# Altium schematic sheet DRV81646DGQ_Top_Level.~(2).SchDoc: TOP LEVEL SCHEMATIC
size 431 x 279 mm; Date: Not shown in title block; ApprovedBy: Not shown in title block; CheckedBy: Not shown in title block; Author: Not shown in title block; CompanyName: Not shown in title block; DrawnBy: Mojtaba Afshar; Engineer: Not shown in title block; Organization: Not shown in title block; Address1: Not shown in title block; Address2: Not shown in title block; Address3: Not shown in title block; Address4: Not shown in title block; DocumentNumber: 2; Revision: Use project parameter SCH_Rev; SheetNumber: 0; SheetTotal: 5; PageSetup: Record=PageOptions¦CenterHorizontal=True¦CenterVertical=True¦PrintScale=1.00¦XCorrection=1.00¦YCorrection=1.00¦PrintKind=0¦BorderSize=5000000¦LeftOffset=0¦BottomOffset=0¦Orientation=2¦PaperLength=1000¦PaperWidth=1000¦Scale=100¦PaperSource=15¦PrintQuality=600¦MediaType=1¦DitherType=10¦PaperKind=Letter¦PrintScaleMode=1
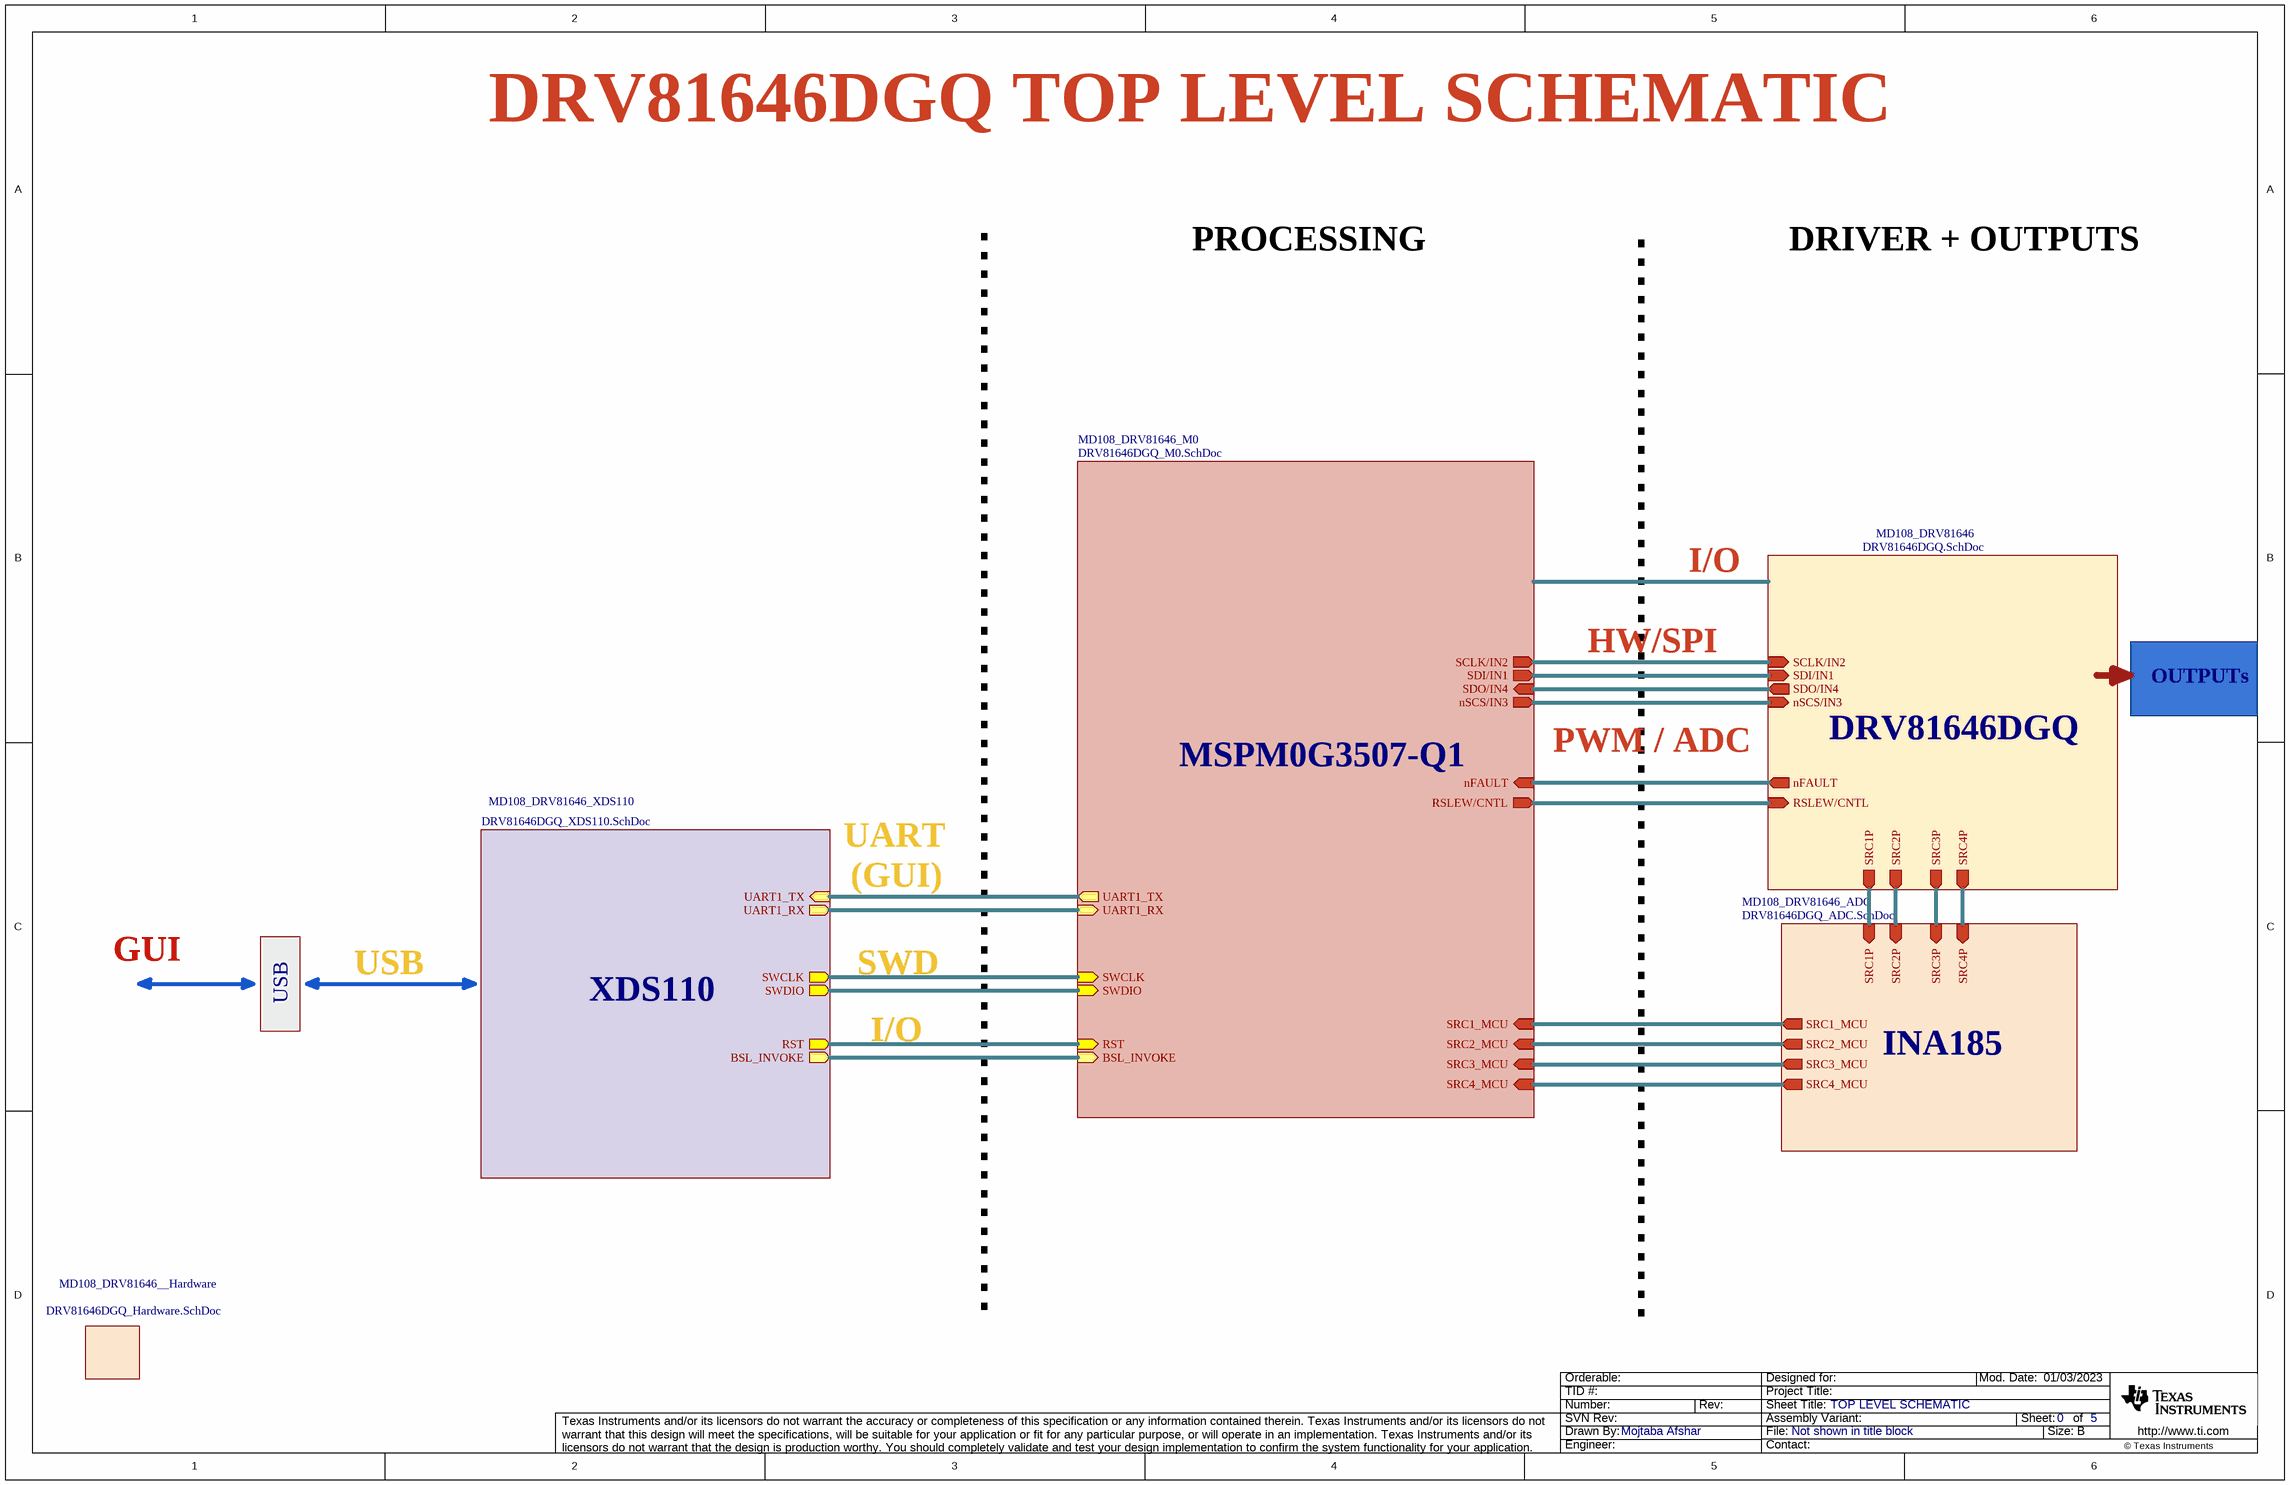
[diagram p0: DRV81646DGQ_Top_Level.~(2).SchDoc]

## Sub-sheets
MD108_DRV81646 = DRV81646DGQ.SchDoc: nFAULT (out), SDI/IN1 (in), SDO/IN4 (out), SCLK/IN2 (in), nSCS/IN3 (in), RSLEW/CNTL (in), SRC1P (out), SRC2P (out), SRC3P (out), SRC4P (out)
MD108_DRV81646__Hardware = DRV81646DGQ_Hardware.SchDoc: no entries
MD108_DRV81646_ADC = DRV81646DGQ_ADC.SchDoc: SRC1P (in), SRC2P (in), SRC3P (in), SRC4P (in), SRC1_MCU (out), SRC2_MCU (out), SRC3_MCU (out), SRC4_MCU (out)
MD108_DRV81646_M0 = DRV81646DGQ_M0.SchDoc: SWDIO (in), SWCLK (in), nFAULT (in), SDI/IN1 (out), SDO/IN4 (in), SCLK/IN2 (out), RST (in), nSCS/IN3 (out), UART1_TX (out), UART1_RX (in), BSL_INVOKE (in), RSLEW/CNTL (out), SRC1_MCU (in), SRC2_MCU (in), SRC3_MCU (in), SRC4_MCU (in)
MD108_DRV81646_XDS110 = DRV81646DGQ_XDS110.SchDoc: SWDIO (out), SWCLK (out), RST (out), UART1_RX (out), UART1_TX (in), BSL_INVOKE (out)

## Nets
(unnamed): sheet MD108_DRV81646_XDS110/SWDIO, sheet MD108_DRV81646_M0/SWDIO
(unnamed): sheet MD108_DRV81646_XDS110/SWCLK, sheet MD108_DRV81646_M0/SWCLK  [a separate net that carries the same name]
(unnamed): sheet MD108_DRV81646_XDS110/RST, sheet MD108_DRV81646_M0/RST  [a separate net that carries the same name]
(unnamed): sheet MD108_DRV81646_XDS110/UART1_RX, sheet MD108_DRV81646_M0/UART1_RX  [a separate net that carries the same name]
(unnamed): sheet MD108_DRV81646_XDS110/UART1_TX, sheet MD108_DRV81646_M0/UART1_TX  [a separate net that carries the same name]
(unnamed): sheet MD108_DRV81646_XDS110/BSL_INVOKE, sheet MD108_DRV81646_M0/BSL_INVOKE  [a separate net that carries the same name]
(unnamed): sheet MD108_DRV81646_M0/nFAULT, sheet MD108_DRV81646/nFAULT  [a separate net that carries the same name]
(unnamed): sheet MD108_DRV81646_M0/SDI/IN1, sheet MD108_DRV81646/SDI/IN1  [a separate net that carries the same name]
(unnamed): sheet MD108_DRV81646_M0/SDO/IN4, sheet MD108_DRV81646/SDO/IN4  [a separate net that carries the same name]
(unnamed): sheet MD108_DRV81646_M0/SCLK/IN2, sheet MD108_DRV81646/SCLK/IN2  [a separate net that carries the same name]
(unnamed): sheet MD108_DRV81646_M0/nSCS/IN3, sheet MD108_DRV81646/nSCS/IN3  [a separate net that carries the same name]
(unnamed): sheet MD108_DRV81646_M0/RSLEW/CNTL, sheet MD108_DRV81646/RSLEW/CNTL  [a separate net that carries the same name]
(unnamed): sheet MD108_DRV81646_M0/SRC1_MCU, sheet MD108_DRV81646_ADC/SRC1_MCU  [a separate net that carries the same name]
(unnamed): sheet MD108_DRV81646_M0/SRC2_MCU, sheet MD108_DRV81646_ADC/SRC2_MCU  [a separate net that carries the same name]
(unnamed): sheet MD108_DRV81646_M0/SRC3_MCU, sheet MD108_DRV81646_ADC/SRC3_MCU  [a separate net that carries the same name]
(unnamed): sheet MD108_DRV81646_M0/SRC4_MCU, sheet MD108_DRV81646_ADC/SRC4_MCU  [a separate net that carries the same name]
(unnamed): sheet MD108_DRV81646/SRC1P, sheet MD108_DRV81646_ADC/SRC1P  [a separate net that carries the same name]
(unnamed): sheet MD108_DRV81646/SRC2P, sheet MD108_DRV81646_ADC/SRC2P  [a separate net that carries the same name]
(unnamed): sheet MD108_DRV81646/SRC3P, sheet MD108_DRV81646_ADC/SRC3P  [a separate net that carries the same name]
(unnamed): sheet MD108_DRV81646/SRC4P, sheet MD108_DRV81646_ADC/SRC4P  [a separate net that carries the same name]

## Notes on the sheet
- DRV81646DGQ TOP LEVEL SCHEMATIC
- PROCESSING
- DRIVER + OUTPUTS
- I/O
- HW/SPI
- OUTPUTs
- PWM / ADC
- DRV81646DGQ
- MSPM0G3507-Q1
- UART
- (GUI)
- GUI
- USB
- XDS110
- SWD
- INA185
